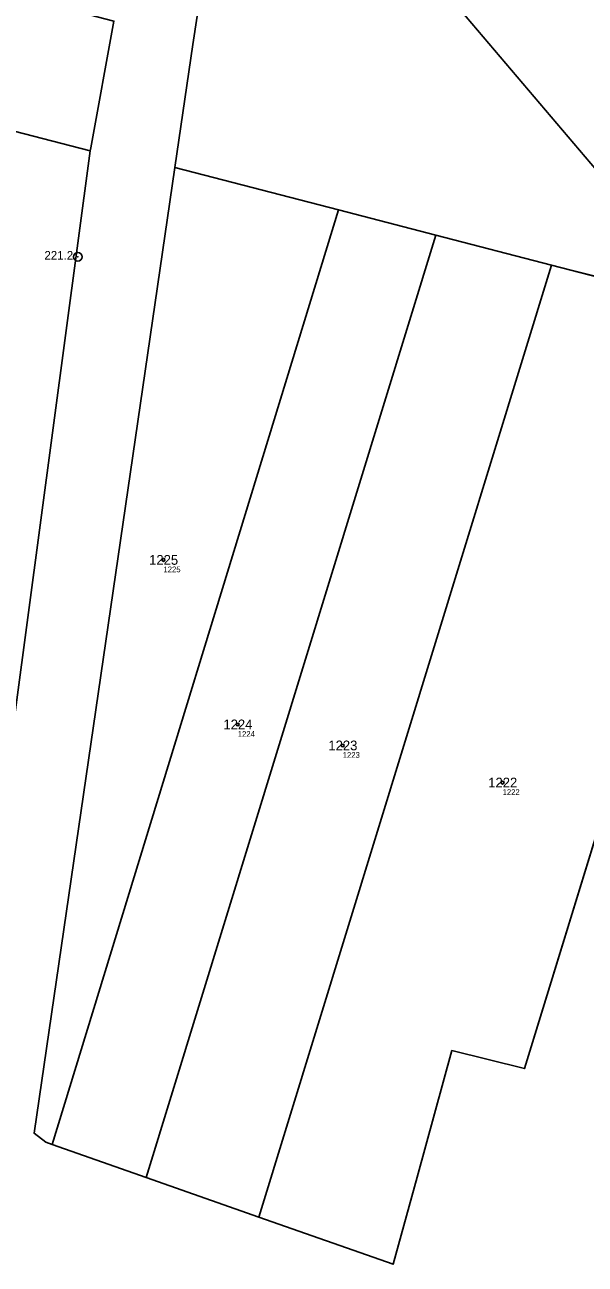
# Model space of a CAD drawing. Extents: x -781091 to -780384, y -1093010 to -1092030.
# Drawn here: x -780824.6 to -780727, y -1092996.9 to -1092780.8 of the extents above; entities that cross this region are included whole.
import ezdxf

# ---------------------------------------------------------------- set-up
doc = ezdxf.new("R2010")
doc.units = 0
for name, color, linetype in [('Vrstva 1', 7, 'Continuous'), ('Vrstva 2', 7, 'Continuous'), ('Vrstva 50', 7, 'Continuous'), ('Vrstva 51', 7, 'Continuous'), ('Vrstva 6', 7, 'Continuous'), ('Vrstva 8', 7, 'Continuous')]:
    doc.layers.add(name, color=color, linetype=linetype)

msp = doc.modelspace()

# ---------------------------------------------------------------- linework, layer by layer
at = {"layer": 'Vrstva 1'}
for p, q in [((-780813.18, -1092802.8), (-780826.45, -1092799.39)), ((-780798.44, -1092805.72), (-780769.96, -1092813.09)), ((-780769.96, -1092813.09), (-780819.8, -1092975.97)), ((-780769.96, -1092813.09), (-780753, -1092817.48)), ((-780753, -1092817.48), (-780803.44, -1092981.73)), ((-780753, -1092817.48), (-780732.85, -1092822.7)), ((-780732.85, -1092822.7), (-780783.81, -1092988.64)), ((-780732.85, -1092822.7), (-780697.38, -1092831.88)), ((-780697.38, -1092831.88), (-780737.57, -1092962.77))]:
    msp.add_line(p, q, dxfattribs=at)
for points in [[(-780765.06, -1092581.92), (-780774.6, -1092648.53), (-780795.32, -1092784.28), (-780798.44, -1092805.72)], [(-780813.18, -1092802.8), (-780813.11, -1092802.28), (-780809.07, -1092780.17)], [(-780827.7, -1092909.92), (-780826.19, -1092900.24), (-780813.18, -1092802.8)], [(-780798.44, -1092805.72), (-780822.97, -1092974.02), (-780820.93, -1092975.57)]]:
    msp.add_lwpolyline(points, dxfattribs=at)
at = {"layer": 'Vrstva 50'}
for centre in [(-780800.43, -1092874.09994), (-780787.49, -1092902.77994), (-780769.21, -1092906.43994), (-780741.37, -1092912.90994)]:
    msp.add_circle(centre, 0.25, dxfattribs=at)
at = {"layer": 'Vrstva 51'}
for points in [[(-780765.06, -1092581.92), (-780774.6, -1092648.53), (-780795.32, -1092784.28), (-780798.44, -1092805.72), (-780769.96, -1092813.09), (-780753, -1092817.48), (-780732.85, -1092822.7), (-780697.38, -1092831.88), (-780595.78, -1092858.19), (-780621.09, -1092702.81), (-780643.35, -1092566.12), (-780644.91, -1092566.38), (-780712.05, -1092575.19)], [(-780855.5, -1092791.93), (-780826.45, -1092799.39), (-780813.18, -1092802.8), (-780813.11, -1092802.28), (-780809.07, -1092780.17), (-780848.79, -1092769.81)], [(-780813.18, -1092802.8), (-780826.45, -1092799.39), (-780827.43, -1092802.24), (-780840.2, -1092839.35), (-780844.69, -1092852.39), (-780859.13, -1092900.62), (-780827.7, -1092909.92), (-780826.19, -1092900.24)], [(-780820.93, -1092975.57), (-780819.8, -1092975.97), (-780769.96, -1092813.09), (-780798.44, -1092805.72), (-780822.97, -1092974.02)], [(-780769.96, -1092813.09), (-780819.8, -1092975.97), (-780803.44, -1092981.73), (-780753, -1092817.48)], [(-780803.44, -1092981.73), (-780783.81, -1092988.64), (-780732.85, -1092822.7), (-780753, -1092817.48)], [(-780750.21, -1092959.6), (-780737.57, -1092962.77), (-780697.38, -1092831.88), (-780732.85, -1092822.7), (-780783.81, -1092988.64), (-780760.45, -1092996.86), (-780756.27, -1092981.67)]]:
    msp.add_lwpolyline(points, close=True, dxfattribs=at)
at = {"layer": 'Vrstva 6'}
msp.add_line((-780688.65, -1092849.19), (-780759.93, -1092764.96), dxfattribs=at)
at = {"layer": 'Vrstva 8'}
for radius in [0.75, 0.03]:
    msp.add_circle((-780815.35, -1092821.25982), radius, dxfattribs=at)

# ---------------------------------------------------------------- texts
at = {"layer": 'Vrstva 2'}
for s, p in [('1225', (-780802.937, -1092874.95)), ('1224', (-780789.997, -1092903.63)), ('1223', (-780771.717, -1092907.29)), ('1222', (-780743.877, -1092913.76))]:
    msp.add_text(s, height=1.699998, dxfattribs=at).set_placement(p)
at = {"layer": 'Vrstva 50'}
for s, p in [('1225', (-780800.43, -1092876.256)), ('1224', (-780787.49, -1092904.936)), ('1223', (-780769.21, -1092908.596)), ('1222', (-780741.37, -1092915.066))]:
    msp.add_text(s, height=0.999996, dxfattribs=at).set_placement(p)
at = {"layer": 'Vrstva 8'}
msp.add_text('221.2', height=1.499994, dxfattribs=at).set_placement((-780821.17, -1092821.76))

doc.saveas('drawing.dxf')
